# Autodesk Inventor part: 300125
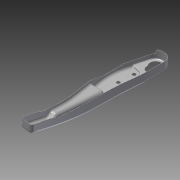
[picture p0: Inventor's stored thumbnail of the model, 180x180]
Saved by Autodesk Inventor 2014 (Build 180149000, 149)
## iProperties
Created: 2007-12
Part Number: 300125
Document SubType Name: Modeling
Designer: MM
Density: 7.85 g/cm^3
Mass: 603.846 g
Surface Area: 1574.23 cm^2
Volume: 76.9231 cm^3
Material: Steel
Description: LEFT SIDE BACK MEMBER
Appearance: Steel
Component Category: Back Component
Author: MM
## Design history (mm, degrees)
node "300334" dims "d0" = 10
  workplane "Work Plane3"
body "Solid1"
tag "TaggingFeature2"
workplane "Work Plane2"
feature "DerivedBody::D-300334" dims "d0" = 10
